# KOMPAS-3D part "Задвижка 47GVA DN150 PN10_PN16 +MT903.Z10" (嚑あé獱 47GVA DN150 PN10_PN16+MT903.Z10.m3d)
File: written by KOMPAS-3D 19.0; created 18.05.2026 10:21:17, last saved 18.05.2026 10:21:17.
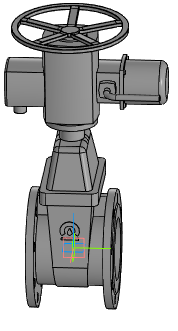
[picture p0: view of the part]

Document properties: Автор: Энергия; Полное имя файла: ..\Задвижка 47GVA DN50_DN1000+MT903.Z\Задвижка 47GVA DN150 PN10_PN16+MT903.Z10.a3d

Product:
- Part/product: Задвижка 47GVA DN150 PN10_PN16 +MT903.Z10
    Масса: 107.086
  - Body: Электропривод MT903.Z05-15
      Масса: 49.8062
  - Body: Задвижка 47GVA DN150 PN10_PN16 без исполнит. мех.
      Масса: 57.2801

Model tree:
1. Операция без истории:1
2. Операция без истории:2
